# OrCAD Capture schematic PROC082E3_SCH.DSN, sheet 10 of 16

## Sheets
10 14. CLOCK BUFFER: size C; title: CLOCK BUFFER
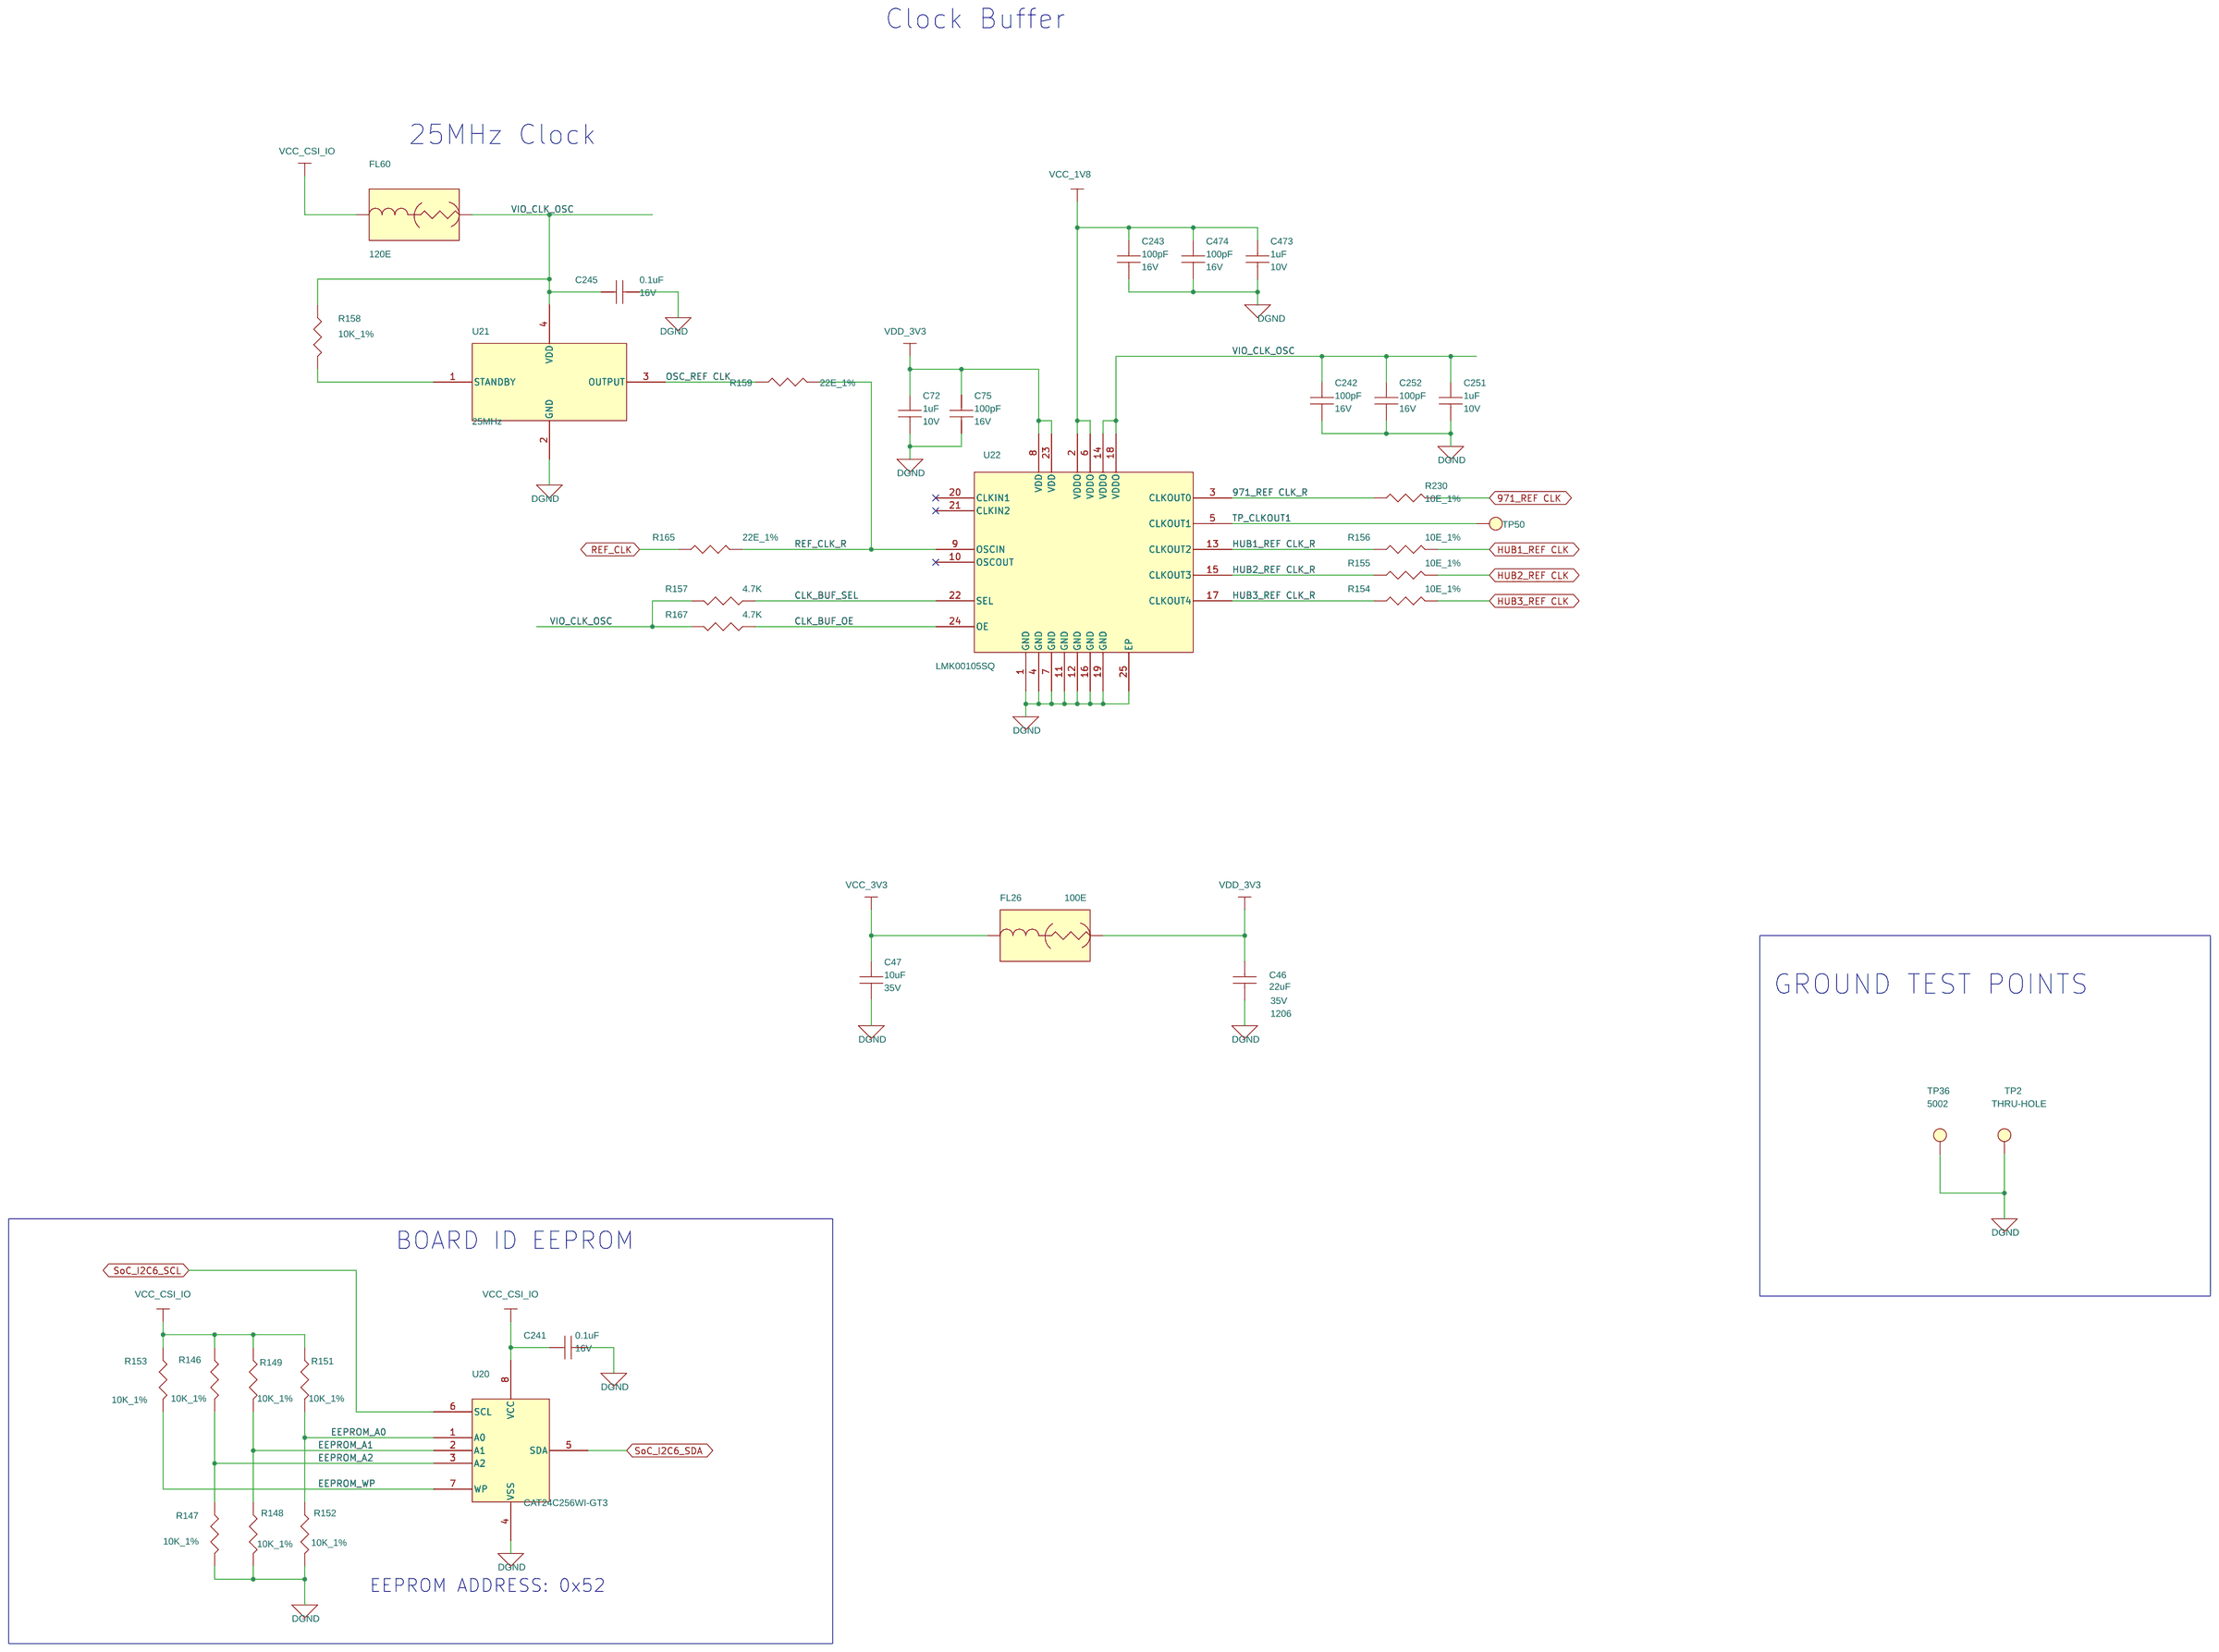
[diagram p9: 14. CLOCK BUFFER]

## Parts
C46  22uF  [CAP1206_2]
C47  10uF  [CAP1206_1]
C72  1uF  [CAP0402_0-75]
C75  100pF  [CAP0402_0-75]
C241  0.1uF  [CAP0402_0-75]
C242  100pF  [CAP0402_0-75]
C243  100pF  [CAP0402_0-75]
C245  0.1uF  [CAP0402_0-75]
C251  1uF  [CAP0402_0-75]
C252  100pF  [CAP0402_0-75]
C473  1uF  [CAP0402_0-75]
C474  100pF  [CAP0402_0-75]
FL26  100E  [EMIFIL_BLM18R_0603]
FL60  120E  [EMIFIL_BLM15A_0402_0-6]
R146  10K_1%  [RES0402_0-5]
R147  10K_1%  [RES0402_0-5]
R148  10K_1%  [RES0402_0-5]
R149  10K_1%  [RES0402_0-5]
R151  10K_1%  [RES0402_0-5]
R152  10K_1%  [RES0402_0-5]
R153  10K_1%  [RES0402_0-5]
R154  10E_1%  [RES0402_0-5]
R155  10E_1%  [RES0402_0-5]
R156  10E_1%  [RES0402_0-5]
R157  4.7K  [RES0402_0-5]
R158  10K_1%  [RES0402_0-5]
R159  22E_1%  [RES0402_0-5]
R165  22E_1%  [RES0402_0-5]
R167  4.7K  [RES0402_0-5]
R230  10E_1%  [RES0402_0-5]
TP2  THRU HOLE  [TP_40X65]
TP36  5002  [TP_CIR67D40_TH_4-6]
TP50  TP40_SMD  [TP40_SMD]
U20  CAT24C256WI-GT3  [SOIC8_1-8]
U21  25MHz  [OSC4_ASDMB_100X85_SMD]
U22  LMK00105SQ  [WQFN24_19-68_160X160]

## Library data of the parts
C46 = CAP: CAP CERAMIC 22uF 35V 20% X5R 1206; Chkd/date: MANIRAJA/130318; Crtd /date: MANIRAJA/130318; Custom_Duty: 15%; Customs_HS_Code: 85322990; Distributor_name: DIGIKEY; Distributor_part_number: 445-8045-1-ND; Footprint Path: Y:\MIS_DATABASE\Library\ALTIUM_TOOL\PCB_FOOTPRINTS\Altium_Footprint_Lib.PcbLib; Height: 1.80MM; Library Path: Y:\MIS_DATABASE\Library\ALTIUM_TOOL\SCHEMATICS_PARTS\MS_DISCRETE_Library.schlib; Mfr_name: TDK CORPORATION; Mfr_part_number: C3216X5R1V226M160AC; Mistral Part No: 120018030003-R; Package: 1206; Part_type: CAPACITORS\CERAMIC; Project: TI_SVB_MAXWELL_VPS; RoHS: RoHS; Temperature: -55°C+85°C; Tolerance: 20%; Voltage: 35V; Wattage: NA; Weight: 16.2mg; Datasheet: Y:\MIS_DATABASE\DATASHEETS\CAPACITORS\C3216X5R1V226M160AC.PDF
C47 = CAP: CAP CERAMIC 10uF 35V 10% X5R 1206; Chkd/date: MANIRAJA/130618; Crtd /date: MANIRAJA/130618; Custom_Duty: 15%; Customs_HS_Code: 85322990; Distributor_name: DIGIKEY; Distributor_part_number: 490-9964-1-ND; Footprint Path: Y:\MIS_DATABASE\Library\ALTIUM_TOOL\PCB_FOOTPRINTS\Altium_Footprint_Lib.PcbLib; Height: 0.95MM; Library Path: Y:\MIS_DATABASE\Library\ALTIUM_TOOL\SCHEMATICS_PARTS\MS_DISCRETE_Library.schlib; Mfr_name: MURATA; Mfr_part_number: GRM319R6YA106KA12D; Mistral Part No: 120018060022-R; Package: 1206; Part_type: CAPACITORS\CERAMIC; Project: MYTHIC_PCIE_DB; RoHS: RoHS; Temperature: -55°C+85°C; Tolerance: 10%; Voltage: 35V; Wattage: NA; Weight: 40mg; Datasheet: Y:\MIS_DATABASE\DATASHEETS\CAPACITORS\GRM319R6YA106KA12D.PDF
C72 C251 C473 = CAP: CAP CERAMIC 1uF 10V 10% X7S AUTO 0402; Chkd/date: MANIRAJA/100918; Crtd /date: ALVY/100918; Custom_Duty: 15%; Customs_HS_Code: 85322990; Distributor_name: DIGIKEY; Distributor_part_number: 490-13409-1-ND; Footprint Path: Y:\MIS_DATABASE\Library\ALTIUM_TOOL\PCB_FOOTPRINTS\Altium_Footprint_Lib.PcbLib; Footprint Ref: CAP0402_0-5; Height: 0.70MM; Library Path: Y:\MIS_DATABASE\Library\ALTIUM_TOOL\SCHEMATICS_PARTS\MS_DISCRETE_Library.schlib; Mfr_name: MURATA; Mfr_part_number: GCM155C71A105KE38D; Mistral Part No: 120018090021-R; Package: 0402; Part_type: CAPACITORS\CERAMIC; Project: SMART-M_SCRIPTALK_PB; RoHS: RoHS; Temperature: -55°C+125°C; Tolerance: 10%; Voltage: 10V; Wattage: NA; Weight: 6mg; Datasheet: Y:\MIS_DATABASE\DATASHEETS\CAPACITORS\MURATA-GCM-SER.PDF
C75 C242 C243 C252 C474 = CAP: CAP CERAMIC 100pF 16V 10% X7R 0402; Chkd/date: VASANTHA/091215; Crtd /date: VASANTHA/091215; Custom_Duty: 15%; Customs_HS_Code: 85322990; Distributor_name: DIGIKEY; Distributor_part_number: 478-7887-1-ND; Footprint Path: Y:\MIS_DATABASE\Library\ALTIUM_TOOL\PCB_FOOTPRINTS\Altium_Footprint_Lib.PcbLib; Height: 0.56MM; Library Path: Y:\MIS_DATABASE\Library\ALTIUM_TOOL\SCHEMATICS_PARTS\MS_DISCRETE_Library.schlib; Mfr_name: AVX CORPORATION; Mfr_part_number: 0402YC101KAT2A; Mistral Part No: 120015120003-R; Package: 0402; Part_type: CAPACITORS\CERAMIC; Project: TI_VLAN_SWITCH; RoHS: RoHS; Temperature: -55°C+125°C; Tolerance: 10%; Voltage: 16V; Wattage: NA; Weight: 0.65mg; Datasheet: Y:\MIS_DATABASE\DATASHEETS\CAPACITORS\AVX_MLC.PDF
C241 C245 = CAP: CAP CERAMIC 0.1uF 16V 5% X7R AUTO 0402; Automotive Alternate_mfr_name: TDK; Automotive Alternate_mfr_part_number: CGA2B1X7R1C104K050BC; Chkd/date: MANIRAJA/241018; Crtd /date: ALVY/241018; Custom_Duty: 15%; Customs_HS_Code: 85322990; Direct Alternate_mfr_name: TDK; Direct Alternate_mfr_part_number: CGA2B1X7R1C104K050BC; Distributor_name: DIGIKEY; Distributor_part_number: 490-16433-1-ND; Footprint Path: Y:\MIS_DATABASE\Library\ALTIUM_TOOL\PCB_FOOTPRINTS\Altium_Footprint_Lib.PcbLib; Height: 0.55MM; Library Path: Y:\MIS_DATABASE\Library\ALTIUM_TOOL\SCHEMATICS_PARTS\MS_DISCRETE_Library.schlib; Mfr_name: MURATA; Mfr_part_number: GCM155R71C104JA55D; Mistral Part No: 120018100055-R; Package: 0402; Part_type: CAPACITORS\CERAMIC; Project: TI_J7ES_EVM_CP; RoHS: RoHS; Temperature: -55°C+125°C; Tolerance: 5%; Voltage: 16V; Wattage: NA; Weight: 6mg; Datasheet: Y:\MIS_DATABASE\DATASHEETS\CAPACITORS\GCM155R71C104JA55D.PDF
FL26 = EMIFILTER_IND: PASSIVE FILTER EMI 100E 2A 0603; Chkd/date: BAVISH/170811; Crtd /date: CHAITHANYA/170811; Custom_Duty: 24%; Customs_HS_Code: 85437099; Distributor_name: DIGIKEY; Distributor_part_number: BLM18EG101TN1D-ND; Footprint Path: Y:\MIS_DATABASE\Library\ALTIUM_TOOL\PCB_FOOTPRINTS\Altium_Footprint_Lib.PcbLib; Height: 0.65MM; Library Path: Y:\MIS_DATABASE\Library\ALTIUM_TOOL\SCHEMATICS_PARTS\MS_FILTER_Library.schlib; Mfr_name: MURATA; Mfr_part_number: BLM18EG101TN1D; Mistral Part No: 130011080028-R; Package: 0603; Part_type: FILTER; Project: CPCI3GADC_CARD; RoHS: RoHS; Temperature: -55°C+125°C; Tolerance: NA; Voltage: NA; Wattage: NA; Weight: NA; Datasheet: Y:\MIS_DATABASE\DATASHEETS\DISCRETES\INDUCTORS\BLM18E.PDF
FL60 = EMIFILTER_IND: IND FERRITE BEAD CHIP 120E 1.3A 0402; Chkd/date: VASANTHA/010117; Crtd /date: CHAITHANYA/150312; Custom_Duty: 24%; Customs_HS_Code: 85437099; Distributor_name: DIGIKEY; Distributor_part_number: 490-5203-1-ND; Footprint Path: Y:\MIS_DATABASE\Library\ALTIUM_TOOL\PCB_FOOTPRINTS\Altium_Footprint_Lib.PcbLib; Height: 0.55MM; Library Path: Y:\MIS_DATABASE\Library\ALTIUM_TOOL\SCHEMATICS_PARTS\MS_FILTER_Library.schlib; Mfr_name: MURATA; Mfr_part_number: BLM15PD121SN1D; Mistral Part No: 130012030043-R; Package: 0402; Part_type: FILTER; Project: GEN_3-8; RoHS: RoHS; Temperature: -55°C+125°C; Tolerance: 25%; Voltage: NA; Wattage: NA; Weight: 0.65mg; Datasheet: Y:\MIS_DATABASE\DATASHEETS\DISCRETES\INDUCTORS\BLM15X-SER.PDF
R146-R149 R151-R153 R158 = RESISTOR: RES 10K 1/16W 1% 0402; Chkd/date: VASANTHA/201216; Crtd /date: GEETHA/290506; Custom_Duty: 15%; Customs_HS_Code: 85332119; Distributor_name: DIGIKEY; Distributor_part_number: 311-10.0KLRTR-ND; Footprint Path: Y:\MIS_DATABASE\Library\ALTIUM_TOOL\PCB_FOOTPRINTS\Altium_Footprint_Lib.PcbLib; Height: 0.40MM; Library Path: Y:\MIS_DATABASE\Library\ALTIUM_TOOL\SCHEMATICS_PARTS\MS_DISCRETE_Library.schlib; Mfr_name: YAGEO AMERICA; Mfr_part_number: RC0402FR-0710KL; Mistral Part No: 110015090015-R; Package: 0402; Part_type: RESISTORS\FIXED; Project: VOCERA; RoHS: RoHS; Temperature: -55°C+155°C; Tolerance: 1%; Voltage: NA; Wattage: 1/16W; Weight: 0.65mg; Datasheet: Y:\MIS_DATABASE\DATASHEETS\RESISTORS\RCXXXXL-SER_MAR18.PDF
R154-R156 R230 = RESISTOR: RES 10E 1/10W 1% 0402; Chkd/date: VASANTHA/201216; Crtd /date: MAZHAR/120505; Custom_Duty: 15%; Customs_HS_Code: 85332119; Distributor_name: DIGIKEY; Distributor_part_number: P10.0LCT-ND; Footprint Path: Y:\MIS_DATABASE\Library\ALTIUM_TOOL\PCB_FOOTPRINTS\Altium_Footprint_Lib.PcbLib; Height: 0.40MM; Library Path: Y:\MIS_DATABASE\Library\ALTIUM_TOOL\SCHEMATICS_PARTS\MS_DISCRETE_Library.schlib; Mfr_name: PANASONIC-ECG; Mfr_part_number: ERJ-2RKF10R0X; Mistral Part No: 110009030203-R; Package: 0402; Part_type: RESISTORS\FIXED; Project: CTP02_REVA_BASE; RoHS: RoHS; Temperature: -55°C+155°C; Tolerance: 1%; Voltage: NA; Wattage: 1/10W; Weight: 0.8mg; Datasheet: Y:\MIS_DATABASE\DATASHEETS\RESISTORS\PAN-ERJSER_NOV17.PDF
R157 R167 = RESISTOR: RES 4.7K 1/16W 5% 0402; Chkd/date: VASANTHA/281216; Crtd /date: BAVISH/010611; Custom_Duty: 15%; Customs_HS_Code: 85332119; Distributor_name: DIGIKEY; Distributor_part_number: 541-4.7KJCT-ND; Footprint Path: Y:\MIS_DATABASE\Library\ALTIUM_TOOL\PCB_FOOTPRINTS\Altium_Footprint_Lib.PcbLib; Height: 0.40MM; Library Path: Y:\MIS_DATABASE\Library\ALTIUM_TOOL\SCHEMATICS_PARTS\MS_DISCRETE_Library.schlib; Mfr_name: VISHAY; Mfr_part_number: CRCW04024K70JNED; Mistral Part No: 110011060001-R; Package: 0402; Part_type: RESISTORS\FIXED; Project: AM4515_EVM_LCD; RoHS: RoHS; Temperature: -55°C+155°C; Tolerance: 5%; Voltage: NA; Wattage: 1/16W; Weight: 0.65mg; Datasheet: Y:\MIS_DATABASE\DATASHEETS\RESISTORS\CRCW0603.PDF
R159 R165 = RESISTOR: RES 22E 1/16W 1% 0402; Chkd/date: SUHAS/290910; Crtd /date: MAZHAR/090909; Cust_part_number: 4700-80047E; Custom_Duty: 15%; Customs_HS_Code: 85332119; Distributor_name: DIGIKEY; Distributor_part_number: 311-22.0LRCT-ND; Footprint Path: Y:\MIS_DATABASE\Library\ALTIUM_TOOL\PCB_FOOTPRINTS\Altium_Footprint_Lib.PcbLib; Height: 0.40MM; Library Path: Y:\MIS_DATABASE\Library\ALTIUM_TOOL\SCHEMATICS_PARTS\MS_DISCRETE_Library.schlib; Mfr_name: YAGEO AMERICA; Mfr_part_number: RC0402FR-0722RL; Mistral Part No: 110009090004-R; Package: 0402; Part_type: RESISTORS\FIXED; Project: VMEFMCD; RoHS: RoHS; SIGNAL_MODEL: RESISTOR_RES0402_22E_22E; Temperature: -55°C+155°C; Tolerance: 1%; Voltage: NA; Wattage: 1/16W; Weight: 0.65mg; Datasheet: Y:\MIS_DATABASE\DATASHEETS\RESISTORS\RCXXXXL-SER_MAR18.PDF
TP2 = TESTPOINT: TESTPOINT 1.0MM DRILL PTH; Chkd/date: MAZHAR/271211; Crtd /date: SHREESHAIL/041005; Distributor_name: NA; Distributor_part_number: NA; Height: NA; Mfr_name: LOCAL; Mistral Part No: 130009030938; Package: THRU-HOLE; Project: HSE; Datasheet: NA
TP36 = TESTPOINT: ACCESSORIE PC TEST POINT; Chkd/date: VASANTHA/121216; Crtd /date: MANIRAJA/121216; Custom_Duty: NA; Customs_HS_Code: NA; Distributor_name: DIGIKEY; Distributor_part_number: 36-5002-ND; Footprint Path: Y:\MIS_DATABASE\Library\ALTIUM_TOOL\PCB_FOOTPRINTS\Altium_Footprint_Lib.PcbLib; Height: 4.57MM; Library Path: Y:\MIS_DATABASE\Library\ALTIUM_TOOL\SCHEMATICS_PARTS\MS_DISCRETE_Library.schlib; Mfr_name: KEYSTONE; Mistral Part No: 160016120008-R; Package: NA; Part_type: ACCESSORIES; Project: EPOS_EVM; RoHS: RoHS; Temperature: NA; Tolerance: NA; Voltage: NA; Wattage: NA; Weight: NA; Datasheet: Y:\MIS_DATABASE\DATASHEETS\MISC\ACCESSORIES\5002.PDF
TP50 = TESTPOINT: TESTPOINT CIR 40 SMD; Chkd/date: MAZHAR/190505; Crtd /date: MAZHAR/190505; Distributor_name: NA; Distributor_part_number: NA; Footprint Path: Y:\MIS_DATABASE\Library\ALTIUM_TOOL\PCB_FOOTPRINTS\Altium_Footprint_Lib.PcbLib; Height: NA; Library Path: Y:\MIS_DATABASE\Library\ALTIUM_TOOL\SCHEMATICS_PARTS\MS_DISCRETE_Library.schlib; MECHANICAL 3D STEP FILE: NA; Mfr_name: LOCAL; Mistral Part No: 130009030933; Package: SMD; Project: RAINIER-3; RoHS: NA; Temperature: NA; Tolerance: NA; Voltage: NA; Wattage: NA; Weight: NA; Datasheet: NA
U20 = CAT24C256WI-GT3_SOIC8: IC 256K I2C CMOS SERIAL EEPROM SOIC8; Chkd/date: MANIRAJA/130617; Crtd /date: MUDDU/270510; Custom_Duty: 15%; Customs_HS_Code: 85423100; Distributor_name: DIGIKEY; Distributor_part_number: CAT24C256WI-GT3-ND; Height: 1.75MM; Mfr_name: ON SEMICONDUCTOR; Mistral Part No: 141110050004-R; Package: SOIC8; Part_type: ICS\DIGITAL\MEMORY; Project: CENTAURUS; RoHS: RoHS; Temperature: -40°C+85°C; Tolerance: NA; Voltage: NA; Wattage: NA; Weight: 540mg; Datasheet: Y:\MIS_DATABASE\DATASHEETS\ICS\MEMORY\CAT24C256WI.PDF
U21 = OSC4_ASDMB: OSC 25MHz 25ppm SMD; Chkd/date: VASANTHA/091215; Crtd /date: VASANTHA/091215; Custom_Duty: 15%; Customs_HS_Code: 85412900; Distributor_name: DIGIKEY; Distributor_part_number: 535-12145-1-ND; Height: 0.90MM; Mfr_name: ABRACON CORPORATION; Mfr_part_number: ASDMB-25.000MHZ-LR-T; Mistral Part No: 130015120008-R; Package: SMD; Part_type: OSCILLATORS; Project: TI_VLAN_SWITCH; RoHS: RoHS; Temperature: -40°C+85°C; Tolerance: NA; Voltage: NA; Wattage: NA; Weight: NA; Datasheet: Y:\MIS_DATABASE\DATASHEETS\MISC\CRY_OSC\ASDMB.PDF
U22 = LMK00105SQ_WQFN24: IC CLOCK JITTER BUFFER AND LEVEL TRANSLATOR WQFN24; Chkd/date: VASANTHA/16115; Crtd /date: VASANTHA/16115; Custom_Duty: 15%; Customs_HS_Code: 85423100; Distributor_name: DIGIKEY; Distributor_part_number: LMK00105SQ/NOPBCT-ND; Height: 0.80MM; Mfr_name: TEXAS INSTRUMENTS; Mfr_part_number: LMK00105SQ/NOPB; Mistral Part No: 141015110009-R; Package: WQFN24; Part_type: ICS\DIGITAL\PERIPHERAL; Project: TI_VLAN_SWITCH; RoHS: RoHS; Temperature: -40°C+85°C; Tolerance: NA; Voltage: NA; Wattage: NA; Weight: NA; Datasheet: Y:\MIS_DATABASE\DATASHEETS\ICS\DIGITAL\COMBINATIONAL\LMK0400X.PDF

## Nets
DGND: C46.2 C47.2 C72.2 C75.2 C241.2 C242.2 C243.2 C245.2 C251.2 C252.2 C473.2 C474.2 R147.2 R148.2 R152.2 TP2.1(TP) TP36.1(TP) U20.4(VSS) U21.2(GND) U22.1(GND) U22.4(GND) U22.7(GND) U22.11(GND) U22.12(GND) U22.16(GND) U22.19(GND) U22.25(EP) ; also on sheet 4 5 6 7 8 9 11 13 14 15 16
VCC_1V8: C243.1 C473.1 C474.1 U22.2(VDDO) U22.6(VDDO) ; also on sheet 4 5 6 7 11
VCC_3V3: C47.1 FL26.1 ; also on sheet 4 6 11
VCC_CSI_IO: C241.1 FL60.1 R146.1 R149.1 R151.1 R153.1 U20.8(VCC) ; also on sheet 4 5 6 11
VDD_3V3: C46.1 C72.1 C75.1 FL26.2 U22.8(VDD) U22.23(VDD)
971_REF CLK: R230.2 ; also on sheet 7
971_REF CLK_R: R230.1 U22.3(CLKOUT0)
CLK_BUF_OE: R167.1 U22.24(OE)
CLK_BUF_SEL: R157.1 U22.22(SEL)
EEPROM_A0: R151.2 R152.1 U20.1(A0)
EEPROM_A1: R148.1 R149.2 U20.2(A1)
EEPROM_A2: R146.2 R147.1 U20.3(A2)
EEPROM_WP: R153.2 U20.7(WP)
HUB1_REF CLK: R156.2 ; also on sheet 4
HUB1_REF CLK_R: R156.1 U22.13(CLKOUT2)
HUB2_REF CLK: R155.2 ; also on sheet 5
HUB2_REF CLK_R: R155.1 U22.15(CLKOUT3)
HUB3_REF CLK: R154.2 ; also on sheet 6
HUB3_REF CLK_R: R154.1 U22.17(CLKOUT4)
OSC_REF CLK: R159.1 U21.3(OUTPUT)
REF_CLK: R165.1 ; also on sheet 4
REF_CLK_R: R159.2 R165.2 U22.9(OSCIN)
SoC_I2C6_SCL: U20.6(SCL) ; also on sheet 4 5 6 7
SoC_I2C6_SDA: U20.5(SDA) ; also on sheet 4 5 6 7
TP_CLKOUT1: TP50.1(TP) U22.5(CLKOUT1)
VIO_CLK_OSC: C242.1 C245.1 C251.1 C252.1 FL60.2 R157.2 R158.1 R167.2 U21.4(VDD) U22.14(VDDO) U22.18(VDDO)
N23898061: R158.2 U21.1(STANDBY)

Not connected (* = marked no-connect by the designer): U22 10(OSCOUT)* 20(CLKIN1)* 21(CLKIN2)*

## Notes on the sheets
sheet 10
- Clock Buffer
- 25MHz Clock
- GROUND TEST POINTS
- BOARD ID EEPROM
- EEPROM ADDRESS: 0x52
